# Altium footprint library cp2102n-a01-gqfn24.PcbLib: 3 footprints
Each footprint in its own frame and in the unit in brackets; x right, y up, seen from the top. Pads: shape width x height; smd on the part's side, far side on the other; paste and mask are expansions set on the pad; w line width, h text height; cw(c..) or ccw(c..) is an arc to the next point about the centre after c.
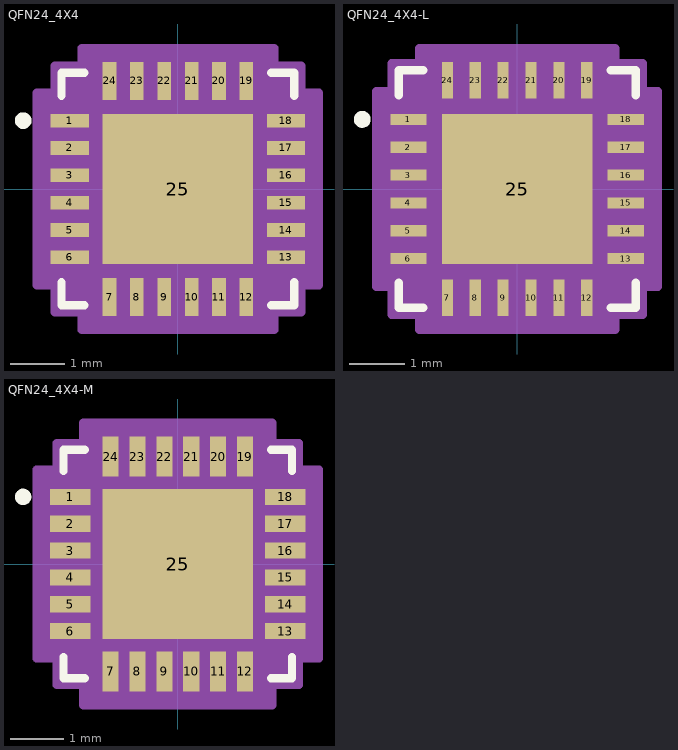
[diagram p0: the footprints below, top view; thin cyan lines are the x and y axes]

## QFN24_4X4 [mm]
pads (25):
  rect 0.7x0.25 smd paste+0 mask+0: 1(-1.975,1.25) 2(-1.975,0.75) 3(-1.975,0.25) 4(-1.975,-0.25) 5(-1.975,-0.75) 6(-1.975,-1.25) 13(1.975,-1.25) 14(1.975,-0.75) 15(1.975,-0.25) 16(1.975,0.25) 17(1.975,0.75) 18(1.975,1.25)
  rect 0.25x0.7 smd paste+0 mask+0: 7(-1.25,-1.975) 8(-0.75,-1.975) 9(-0.25,-1.975) 10(0.25,-1.975) 11(0.75,-1.975) 12(1.25,-1.975) 19(1.25,1.975) 20(0.75,1.975) 21(0.25,1.975) 22(-0.25,1.975) 23(-0.75,1.975) 24(-1.25,1.975)
  rect 2.75x2.75 smd paste-1.362 mask+0: 25(0,0)
Top Overlay:
  circle w0.152: c-2.829,1.25 r0.076
  lines w0.152: -2.127,-1.708 -2.127,-2.127 -1.708,-2.127 ; -2.127,1.708 -2.127,2.127 -1.708,2.127 ; 1.708,-2.127 2.127,-2.127 2.127,-1.708 ; 1.708,2.127 2.127,2.127 2.127,1.708
  text ".Designator" at -3.492,-0.635 h1.27
Top Paste:
  region: -0.1,1.275 -1.275,1.275 -1.275,0.1 -0.1,0.1
  region: -0.1,-0.1 -1.275,-0.1 -1.275,-1.275 -0.1,-1.275
  region: 1.275,1.275 0.1,1.275 0.1,0.1 1.275,0.1
  region: 1.275,-0.1 0.1,-0.1 0.1,-1.275 1.275,-1.275
Mechanical 13:
  circle w0.025: c-1.879,1.25 r0.076
  lines w0.025: -2,0.73 -0.73,2 ; -2,-2 2,-2 2,2 -2,2 -2,-2
  text ".Designator" at -3.492,-0.635 h1.27
Mechanical 15:
  region: -1.758,-2.254 -2.254,-2.254 -2.254,-1.758 -2.579,-1.758 -2.579,1.758 -2.254,1.758 -2.254,2.254 -1.758,2.254 -1.758,2.579 1.758,2.579 1.758,2.254 2.254,2.254 2.254,1.758 2.579,1.758 2.579,-1.758 2.254,-1.758 2.254,-2.254 1.758,-2.254 1.758,-2.579 -1.758,-2.579
  lines w0.152: -2.579,-1.758 -2.254,-1.758 -2.254,-2.254 -1.758,-2.254 -1.758,-2.579 1.758,-2.579 1.758,-2.254 2.254,-2.254 2.254,-1.758 2.579,-1.758 2.579,1.758 2.254,1.758 2.254,2.254 1.758,2.254 1.758,2.579 -1.758,2.579 -1.758,2.254 -2.254,2.254 -2.254,1.758 -2.579,1.758 -2.579,-1.758
3D body "QFN24_4X4.step": height 0.8, standoff 0, extent -2,-2 2,2

## QFN24_4X4-L [mm]
pads (25):
  rect 0.65x0.2 smd paste+0 mask+0: 1(-1.95,1.25) 2(-1.95,0.75) 3(-1.95,0.25) 4(-1.95,-0.25) 5(-1.95,-0.75) 6(-1.95,-1.25) 13(1.95,-1.25) 14(1.95,-0.75) 15(1.95,-0.25) 16(1.95,0.25) 17(1.95,0.75) 18(1.95,1.25)
  rect 0.2x0.65 smd paste+0 mask+0: 7(-1.25,-1.95) 8(-0.75,-1.95) 9(-0.25,-1.95) 10(0.25,-1.95) 11(0.75,-1.95) 12(1.25,-1.95) 19(1.25,1.95) 20(0.75,1.95) 21(0.25,1.95) 22(-0.25,1.95) 23(-0.75,1.95) 24(-1.25,1.95)
  rect 2.7x2.7 smd paste-1.337 mask+0: 25(0,0)
Top Overlay:
  circle w0.152: c-2.779,1.25 r0.076
  lines w0.152: -2.127,-1.683 -2.127,-2.127 -1.683,-2.127 ; -2.127,1.683 -2.127,2.127 -1.683,2.127 ; 1.683,-2.127 2.127,-2.127 2.127,-1.683 ; 1.683,2.127 2.127,2.127 2.127,1.683
  text ".Designator" at -3.492,-0.635 h1.27
Top Paste:
  region: -0.1,1.25 -1.25,1.25 -1.25,0.1 -0.1,0.1
  region: -0.1,-0.1 -1.25,-0.1 -1.25,-1.25 -0.1,-1.25
  region: 1.25,1.25 0.1,1.25 0.1,0.1 1.25,0.1
  region: 1.25,-0.1 0.1,-0.1 0.1,-1.25 1.25,-1.25
Mechanical 13:
  circle w0.025: c-1.879,1.25 r0.076
  lines w0.025: -2,0.73 -0.73,2 ; -2,-2 2,-2 2,2 -2,2 -2,-2
  text ".Designator" at -3.492,-0.635 h1.27
Mechanical 15:
  region: -1.758,-2.254 -2.254,-2.254 -2.254,-1.758 -2.529,-1.758 -2.529,1.758 -2.254,1.758 -2.254,2.254 -1.758,2.254 -1.758,2.529 1.758,2.529 1.758,2.254 2.254,2.254 2.254,1.758 2.529,1.758 2.529,-1.758 2.254,-1.758 2.254,-2.254 1.758,-2.254 1.758,-2.529 -1.758,-2.529
  lines w0.152: -2.529,-1.758 -2.254,-1.758 -2.254,-2.254 -1.758,-2.254 -1.758,-2.529 1.758,-2.529 1.758,-2.254 2.254,-2.254 2.254,-1.758 2.529,-1.758 2.529,1.758 2.254,1.758 2.254,2.254 1.758,2.254 1.758,2.529 -1.758,2.529 -1.758,2.254 -2.254,2.254 -2.254,1.758 -2.529,1.758 -2.529,-1.758
3D body "QFN24_4X4.step": height 0.8, standoff 0, extent -2,-2 2,2

## QFN24_4X4-M [mm]
pads (25):
  rect 0.75x0.3 smd paste+0 mask+0: 1(-2,1.25) 2(-2,0.75) 3(-2,0.25) 4(-2,-0.25) 5(-2,-0.75) 6(-2,-1.25) 13(2,-1.25) 14(2,-0.75) 15(2,-0.25) 16(2,0.25) 17(2,0.75) 18(2,1.25)
  rect 0.3x0.75 smd paste+0 mask+0: 7(-1.25,-2) 8(-0.75,-2) 9(-0.25,-2) 10(0.25,-2) 11(0.75,-2) 12(1.25,-2) 19(1.25,2) 20(0.75,2) 21(0.25,2) 22(-0.25,2) 23(-0.75,2) 24(-1.25,2)
  rect 2.8x2.8 smd paste-1.387 mask+0: 25(0,0)
Top Overlay:
  circle w0.152: c-2.879,1.25 r0.076
  lines w0.152: -2.127,-1.733 -2.127,-2.127 -1.733,-2.127 ; -2.127,1.733 -2.127,2.127 -1.733,2.127 ; 1.733,-2.127 2.127,-2.127 2.127,-1.733 ; 1.733,2.127 2.127,2.127 2.127,1.733
  text ".Designator" at -3.492,-0.635 h1.27
Top Paste:
  region: -0.1,1.3 -1.3,1.3 -1.3,0.1 -0.1,0.1
  region: -0.1,-0.1 -1.3,-0.1 -1.3,-1.3 -0.1,-1.3
  region: 1.3,1.3 0.1,1.3 0.1,0.1 1.3,0.1
  region: 1.3,-0.1 0.1,-0.1 0.1,-1.3 1.3,-1.3
Mechanical 13:
  circle w0.025: c-1.879,1.25 r0.076
  lines w0.025: -2,0.73 -0.73,2 ; -2,-2 2,-2 2,2 -2,2 -2,-2
  text ".Designator" at -3.492,-0.635 h1.27
Mechanical 15:
  region: -1.758,-2.254 -2.254,-2.254 -2.254,-1.758 -2.629,-1.758 -2.629,1.758 -2.254,1.758 -2.254,2.254 -1.758,2.254 -1.758,2.629 1.758,2.629 1.758,2.254 2.254,2.254 2.254,1.758 2.629,1.758 2.629,-1.758 2.254,-1.758 2.254,-2.254 1.758,-2.254 1.758,-2.629 -1.758,-2.629
  lines w0.152: -2.629,-1.758 -2.254,-1.758 -2.254,-2.254 -1.758,-2.254 -1.758,-2.629 1.758,-2.629 1.758,-2.254 2.254,-2.254 2.254,-1.758 2.629,-1.758 2.629,1.758 2.254,1.758 2.254,2.254 1.758,2.254 1.758,2.629 -1.758,2.629 -1.758,2.254 -2.254,2.254 -2.254,1.758 -2.629,1.758 -2.629,-1.758
3D body "QFN24_4X4.step": height 0.8, standoff 0, extent -2,-2 2,2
